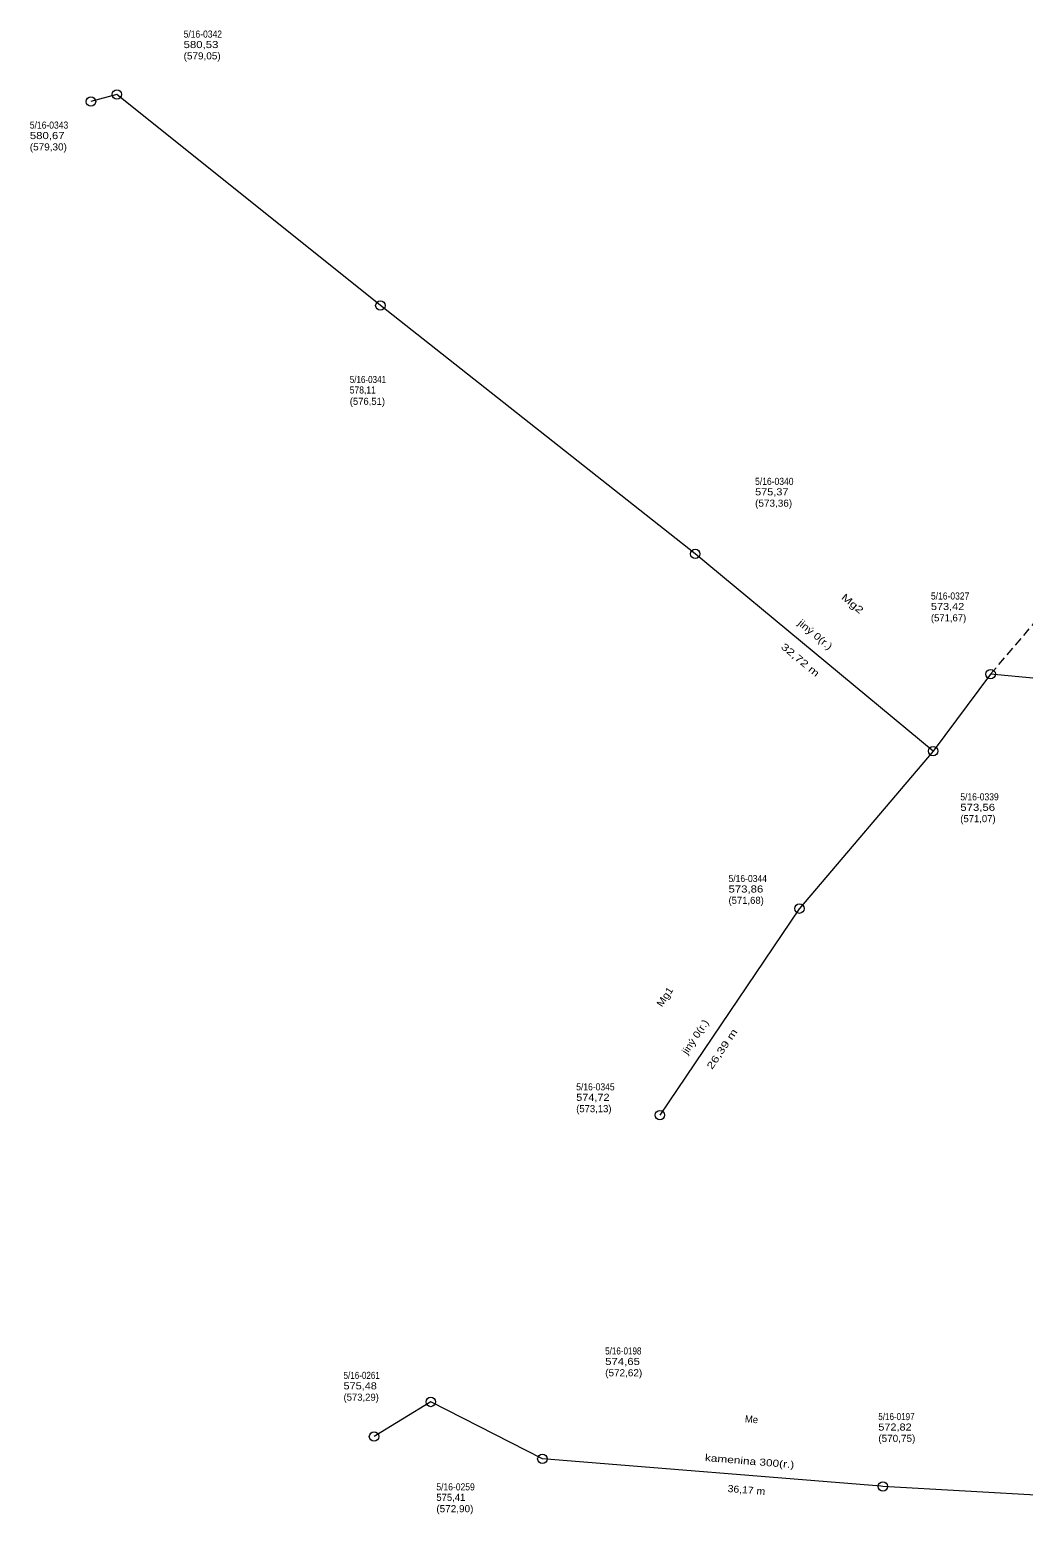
# Model space of a CAD drawing. Extents: x -710854 to -709799, y -1117012 to -1115891.
# Drawn here: x -710060.7 to -709955.5, y -1116086.4 to -1115926.8 of the extents above; entities that cross this region are included whole.
import ezdxf
from ezdxf.enums import TextEntityAlignment as Align

# ---------------------------------------------------------------- set-up
doc = ezdxf.new("R2010")
doc.units = 0
doc.header["$LTSCALE"] = 0.3
doc.linetypes.add('MEDIUM_DASHED', pattern=[4.5, 3, -1.5])
doc.layers.add('38', color=7, linetype='Continuous', lineweight=13)
doc.layers.add('44', color=7, linetype='Continuous', lineweight=13)
doc.layers.add('48', color=7, linetype='Continuous')

msp = doc.modelspace()

# ---------------------------------------------------------------- linework, layer by layer
at = {"layer": '38'}
for p, q in [((-710051.56, -1115933.56), (-710054.307, -1115934.316)), ((-710023.67, -1115955.92), (-710051.56, -1115933.56)), ((-709990.34, -1115982.22), (-710023.67, -1115955.92)), ((-709965.156, -1116003.107), (-709979.307, -1116019.795))]:
    msp.add_line(p, q, dxfattribs=at)
at = {"layer": '38', "linetype": 'MEDIUM_DASHED'}
msp.add_line((-709959.06, -1115994.96), (-709934.18, -1115965.8), dxfattribs=at)
at = {"layer": '38'}
for points in [[(-709959.06, -1115994.96), (-709965.15, -1116003.1), (-709965.156, -1116003.107), (-709990.34, -1115982.22)], [(-709893.99, -1116000.57), (-709922.54, -1115998.23), (-709944.84, -1115996.31), (-709959.06, -1115994.96)], [(-709979.307, -1116019.795), (-709979.32, -1116019.81), (-709994.08, -1116041.66)], [(-710006.52, -1116078.071), (-710006.521, -1116078.071), (-710018.331, -1116072.041), (-710024.34, -1116075.701)], [(-709970.468, -1116080.984), (-709970.691, -1116080.971), (-710006.52, -1116078.071)], [(-709876.147, -1116086.433), (-709876.321, -1116086.421), (-709926.911, -1116083.45), (-709970.468, -1116080.984)]]:
    msp.add_lwpolyline(points, dxfattribs=at)
at = {"layer": '44'}
for centre in [(-710054.307, -1115934.316), (-710051.56, -1115933.56), (-710023.67, -1115955.92), (-709990.34, -1115982.22), (-709959.06, -1115994.96), (-709965.156, -1116003.107), (-709979.307, -1116019.795), (-709994.08, -1116041.66), (-710018.331, -1116072.041), (-710024.34, -1116075.701), (-710006.52, -1116078.071), (-709970.468, -1116080.984)]:
    msp.add_circle(centre, 0.5, dxfattribs=at)

# ---------------------------------------------------------------- texts
at = {"layer": '48'}
for s, width, p in [('5/16-0342', 0.9, (-710044.497, -1115927.546)), ('580,53 ', 1.2, (-710044.497, -1115928.656)), ('(579,05)', 1.05, (-710044.497, -1115929.856)), ('5/16-0343', 0.9, (-710060.779, -1115937.185)), ('580,67 ', 1.2, (-710060.779, -1115938.295)), ('(579,30)', 1.05, (-710060.779, -1115939.495)), ('5/16-0341', 0.85, (-710026.91, -1115964.128)), ('578,11 ', 0.9, (-710026.91, -1115965.238)), ('5/16-0340', 0.9, (-709983.996, -1115974.915)), ('575,37 ', 1.15, (-709983.996, -1115976.025)), ('(573,36)', 1.05, (-709983.996, -1115977.225)), ('5/16-0327', 0.9, (-709965.383, -1115987.058)), ('573,42 ', 1.15, (-709965.383, -1115988.168)), ('5/16-0339', 0.9, (-709962.273, -1116008.328)), ('573,56 ', 1.2, (-709962.273, -1116009.438)), ('5/16-0344', 0.9, (-709986.812, -1116016.978)), ('573,86 ', 1.2, (-709986.812, -1116018.088)), ('5/16-0345', 0.9, (-710002.935, -1116039.044)), ('574,72 ', 1.15, (-710002.935, -1116040.154)), ('5/16-0198', 0.85, (-709999.87, -1116067.013)), ('574,65 ', 1.2, (-709999.87, -1116068.123)), ('5/16-0261', 0.85, (-710027.567, -1116069.601)), ('(572,62)', 1.05, (-709999.87, -1116069.323)), ('575,48 ', 1.15, (-710027.567, -1116070.711)), ('5/16-0197', 0.85, (-709970.953, -1116073.963)), ('572,82 ', 1.15, (-709970.953, -1116075.073)), ('(570,75)', 1.05, (-709970.953, -1116076.273)), ('5/16-0259', 0.9, (-710017.741, -1116081.41)), ('(572,90)', 1.05, (-710017.741, -1116083.72))]:
    msp.add_text(s, height=0.75, dxfattribs=dict(at, width=width)).set_placement(p)
for s, p in [('(576,51)', (-710026.91, -1115966.438)), ('(571,67)', (-709965.383, -1115989.368)), ('(571,07)', (-709962.273, -1116010.638)), ('(571,68)', (-709986.812, -1116019.288)), ('(573,13)', (-710002.935, -1116041.354)), ('(573,29)', (-710027.567, -1116071.911)), ('575,41 ', (-710017.741, -1116082.52))]:
    msp.add_text(s, height=0.75, dxfattribs=at).set_placement(p)
for s, rotation, width, p in [('Mg2', 320.33, 1.35, (-709973.9224, -1115987.7807)), ('jiný 0(r.)', 320.33, 1.2, (-709977.8669, -1115991.0578)), ('32,72 m', 320.33, 1.35, (-709979.4464, -1115993.7374)), ('Mg1', 55.96, 1.15, (-709993.2395, -1116029.3404)), ('jiný 0(r.)', 55.96, 1.15, (-709990.0238, -1116033.5829)), ('26,39 m', 55.96, 1.35, (-709987.1873, -1116034.8689)), ('kamenina 300(r.)', 355.37, 1.25, (-709984.6078, -1116078.682)), ('36,17 m', 355.37, 1.1, (-709984.9418, -1116081.7333))]:
    msp.add_text(s, height=0.75, rotation=rotation, dxfattribs=dict(at, width=width)).set_placement(p, align=Align.CENTER)
msp.add_text('Me', height=0.75, rotation=355.37, dxfattribs=at).set_placement((-709984.4078, -1116074.2526), align=Align.CENTER)

doc.saveas('drawing.dxf')
